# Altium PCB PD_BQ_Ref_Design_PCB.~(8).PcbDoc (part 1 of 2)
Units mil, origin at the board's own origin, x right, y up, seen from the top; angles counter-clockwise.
Board outline 2000 x 3000 mil, 4 copper layers (Top Layer, Signal Layer 1, Signal Layer 2, Bottom Layer), stack 61.2 mil thick; 108 components, 54 nets, 333 pads, 494 vias.
Unrouted connection lines stored in the file: 227.
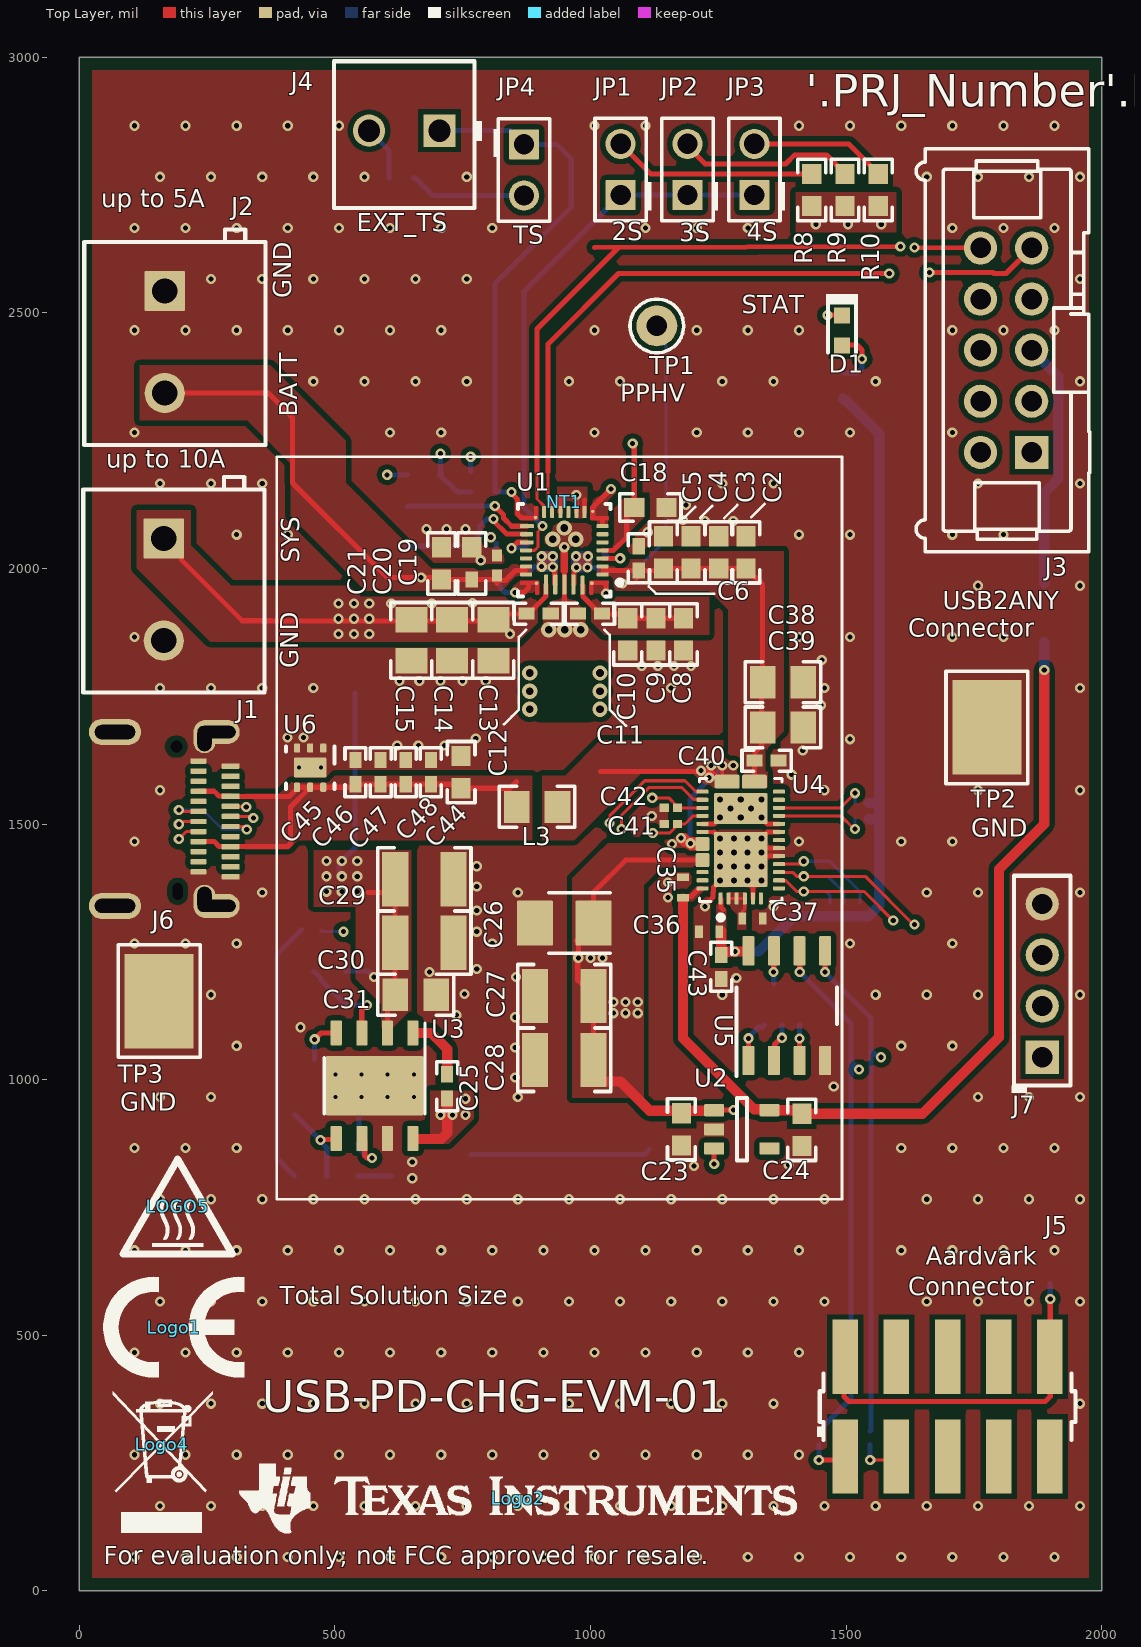
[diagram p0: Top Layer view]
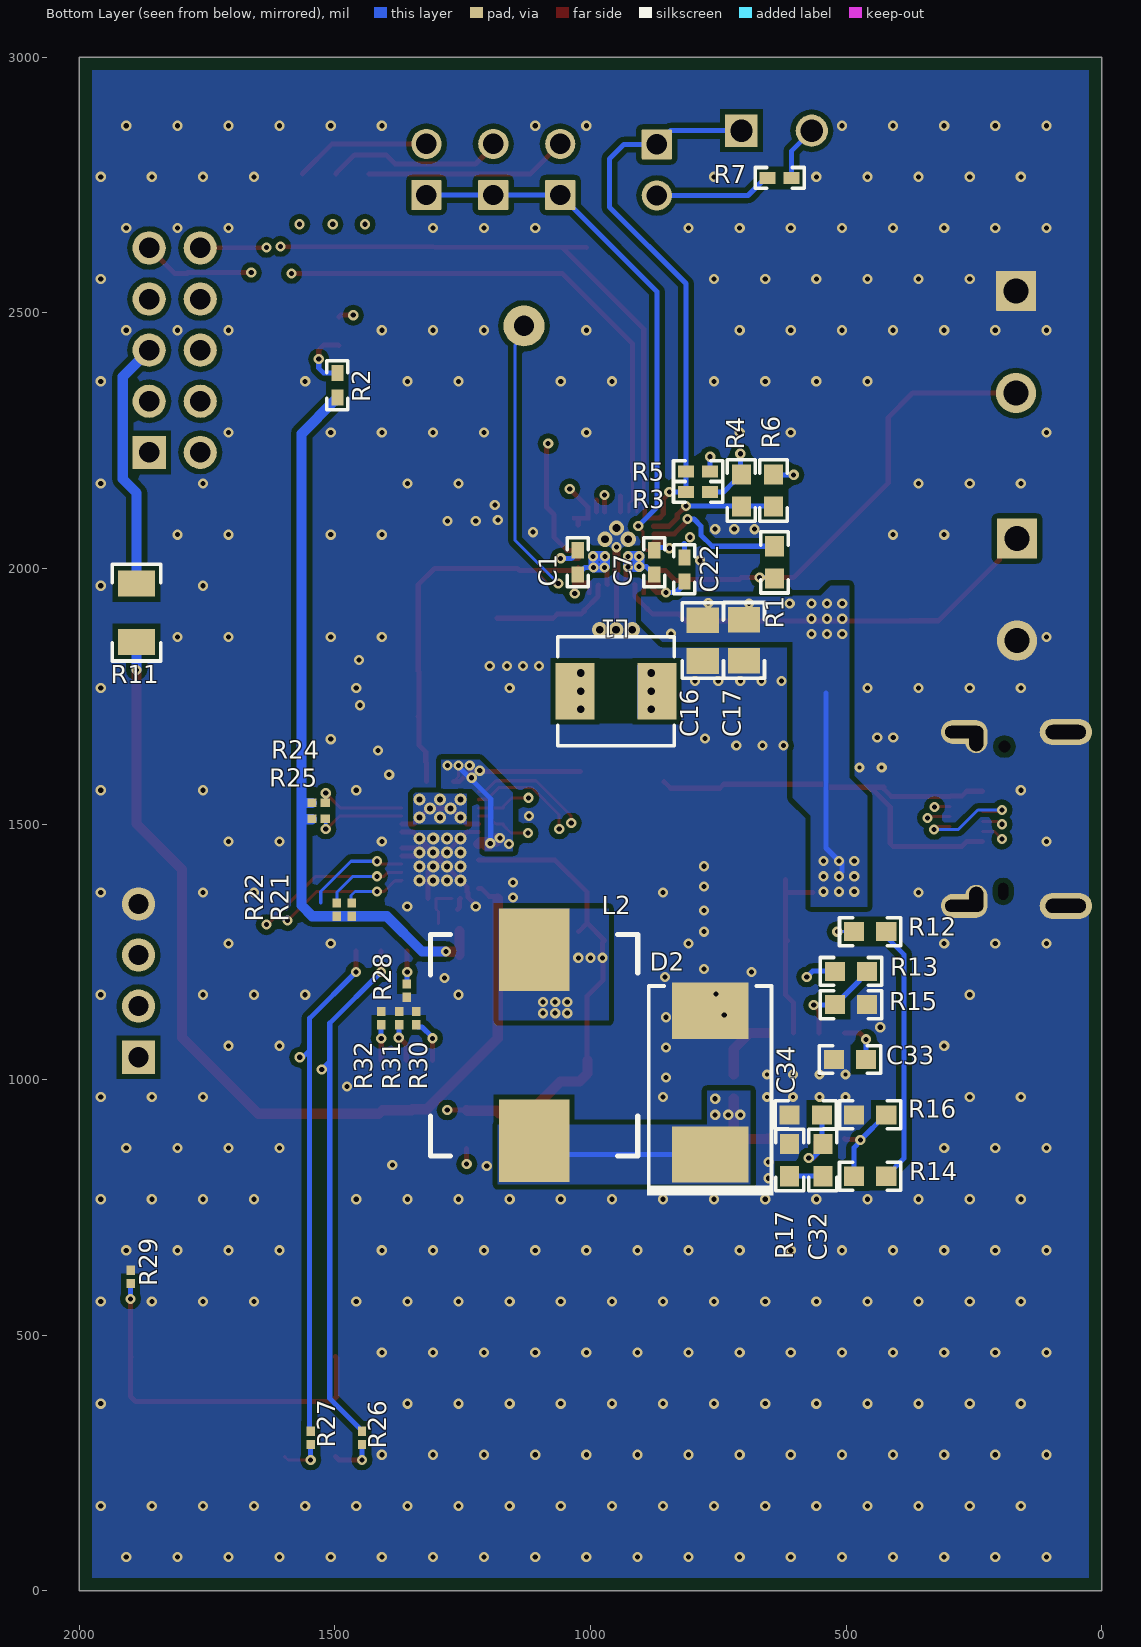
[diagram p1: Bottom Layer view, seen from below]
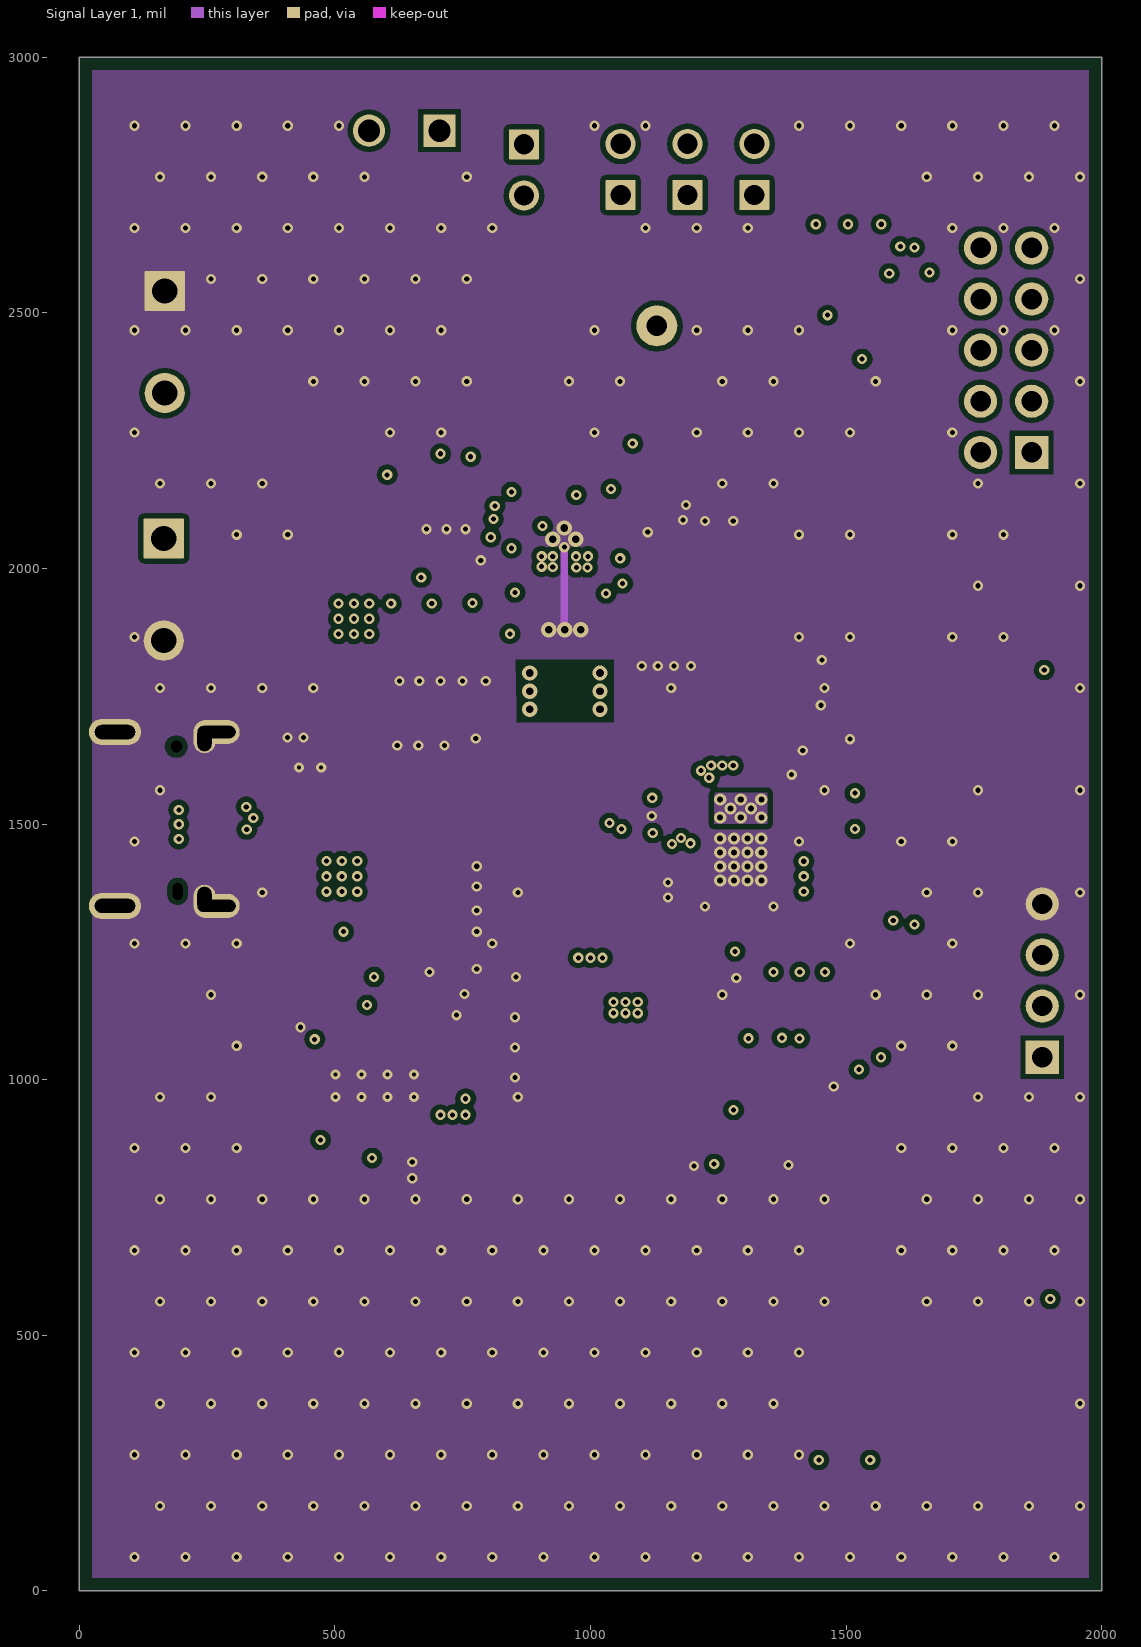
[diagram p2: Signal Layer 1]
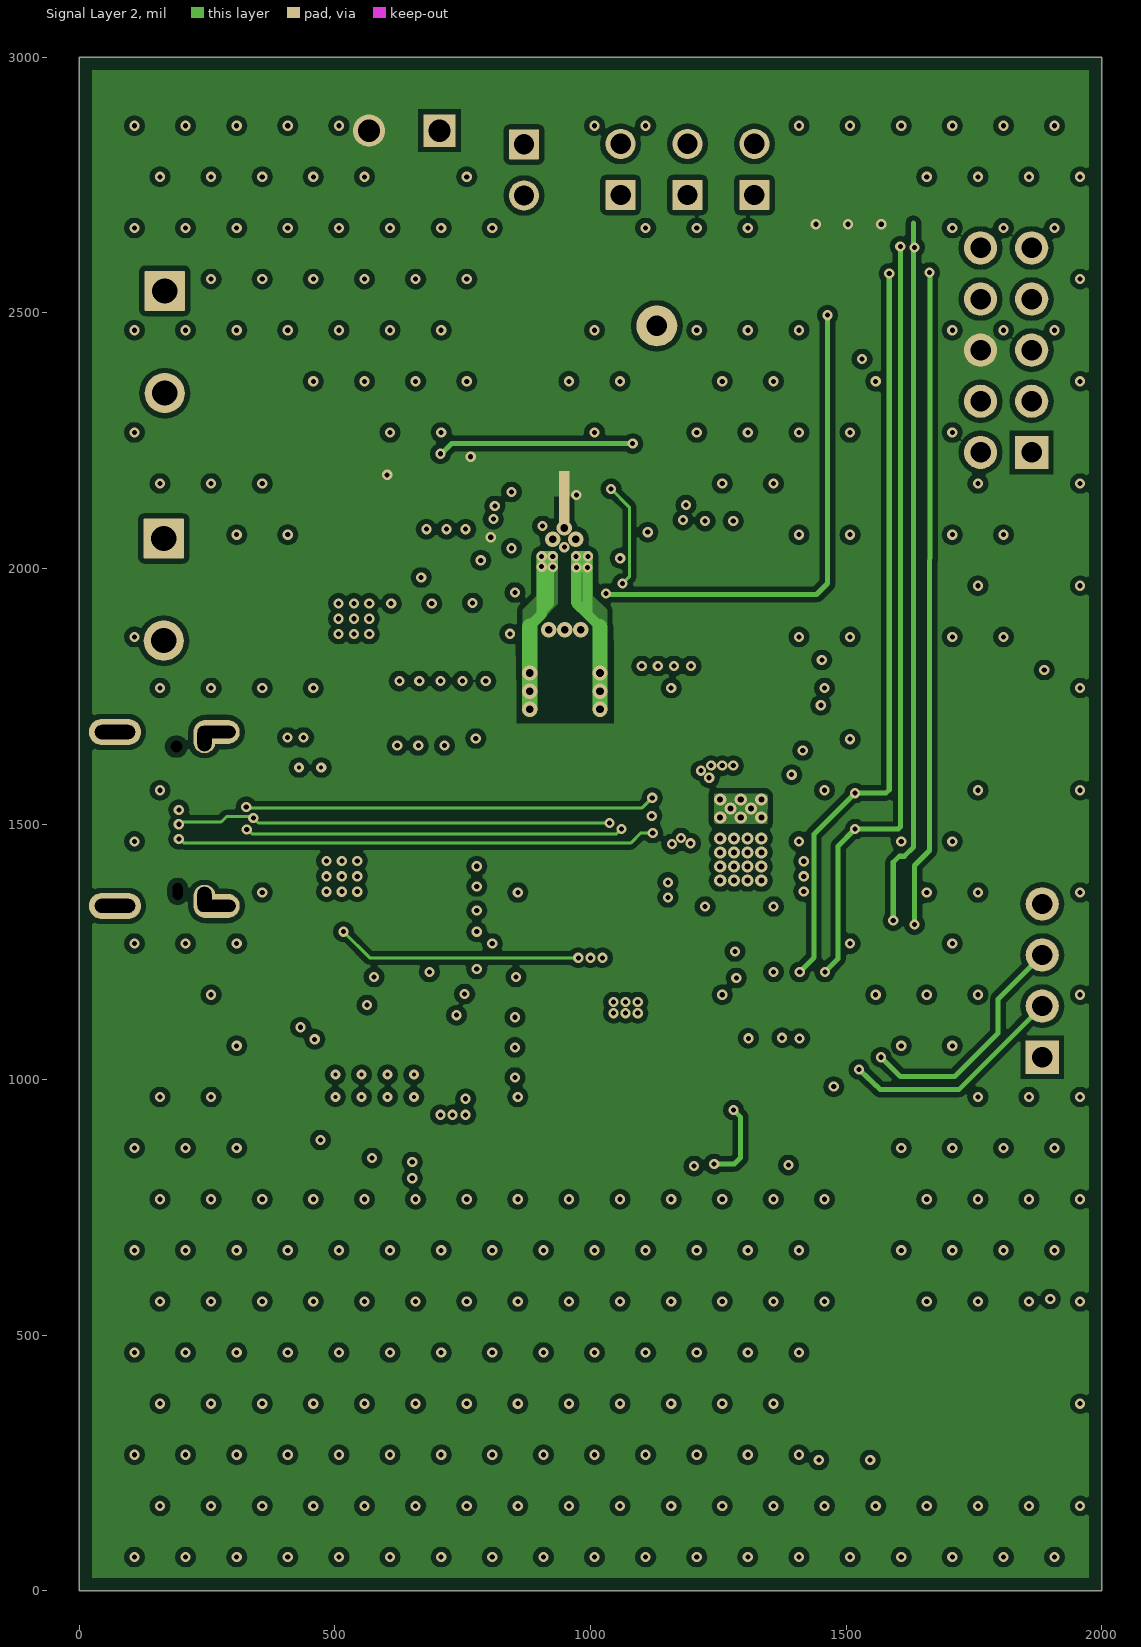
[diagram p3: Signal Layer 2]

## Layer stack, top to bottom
Top Solder: solder mask 0.4, Solder Resist, Dk 3.5
Top Layer: signal copper 2.8
Dielectric 1: prepreg 12, FR-4 High TG, Dk 4.2
Signal Layer 1: signal copper 2.8
Dielectric2: core 26, FR-4 High TG, Dk 4.2
Signal Layer 2: signal copper 2.8
Dielectric3: prepreg 12, FR-4 High TG, Dk 4.2
Bottom Layer: signal copper 2.8
Bottom Solder: solder mask 0.4, Solder Resist, Dk 3.5

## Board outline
0,0 2000,0 2000,3000 0,3000

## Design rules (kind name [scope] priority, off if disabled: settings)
AcuteAngle [All] p1: minimum=4.50000000000000E+0001 checktracksonly=FALSE
AssemblyTestPointUsage [All] p1: valid=2
BoardOutlineClearance BoardOutlineClearance_MountingHoles [OnCopper and InComponentClass('Mounting Holes')] p1: gap=39.37 ignorepadtopadclearanceinfootprint=FALSE
BoardOutlineClearance BoardOutlineClearance_Poly [OnCopper and IsPoly] p2: gap=25 ignorepadtopadclearanceinfootprint=FALSE
BoardOutlineClearance [OnCopper and Not InComponentClass('Logo') and not InComponentClass('FiducialMark') and not InRegion(1000,500,4000,800) and not InPoly] p3: gap=15 ignorepadtopadclearanceinfootprint=FALSE
Clearance Clearance_Keepouts [((IsTrack Or IsArc) And Not InPoly) And IsFree and IsKeepOut vs ((IsTrack Or IsArc) And Not InPoly) And IsFree and IsKeepOut] p1: gap=0 ignorepadtopadclearanceinfootprint=FALSE
Clearance Clearance_Poly [InPolygon] p2: gap=10 ignorepadtopadclearanceinfootprint=TRUE
Clearance Clearance_FiducialMark [IsKeepOut and InComponentClass('FiducialMark') vs IsPad and InComponentClass('FiducialMark')] p3: gap=0 ignorepadtopadclearanceinfootprint=FALSE
Clearance [All] p4: gap=5 ignorepadtopadclearanceinfootprint=TRUE
ComponentClearance ComponentClearance_MountingHoles_FiducialMarks [InComponentClass('Mounting Holes') vs InComponentClass('FiducialMark')] p1: gap=50 collisioncheckmode=3 verticalgap=10 showdistances=FALSE
ComponentClearance ComponentClearance_Shunt [InComponentClass('Header') vs InComponentClass('Shunt')] p2: gap=0 collisioncheckmode=3 verticalgap=0 showdistances=FALSE
ComponentClearance ComponentClearance_Logo [InComponentClass('Logo')] p3: gap=50 collisioncheckmode=3 verticalgap=10 showdistances=FALSE
ComponentClearance ComponentClearance_ScrewToNut [(HasFootprint('NY PMS 440 0025 PH')) vs (HasFootprint('Keystone_1902C'))] p4: gap=5 collisioncheckmode=3 verticalgap=10 showdistances=FALSE
ComponentClearance ComponentClearance_MountingHoles [InComponentClass('Mounting Holes')] p5: gap=250 collisioncheckmode=3 verticalgap=100000 showdistances=FALSE
ComponentClearance ComponentClearance_SmallPassives [HasFootprint('0201*') or HasFootprint('0402*') or HasFootprint('0508') or HasFootprint('0603*') or HasFootprint('0612') or HasFootprint('0805*') or HasFootprint('0815*') or HasFootprint('0830*') or HasFootprint('1206*') or HasFootprint('1210*') or HasFootprint('1808*') or HasFootprint('1812*') or HasFootprint('1825*') or HasFootprint('2010*') or HasFootprint('2220*') or HasFootprint('2225*') or HasFootprint('2512*') or HasFootprint('2728*') or HasFootprint('3518*') vs HasFootprint('0201*') or HasFootprint('0402*') or HasFootprint('0508') or HasFootprint('0603*') or HasFootprint('0612') or HasFootprint('0805*') or HasFootprint('0815*') or HasFootprint('0830*') or HasFootprint('1206*') or HasFootprint('1210*') or HasFootprint('1808*') or HasFootprint('1812*') or HasFootprint('1825*') or HasFootprint('2010*') or HasFootprint('2220*') or HasFootprint('2225*') or HasFootprint('2512*') or HasFootprint('2728*') or HasFootprint('3518*')] p6: gap=14.96 collisioncheckmode=3 verticalgap=10 showdistances=FALSE
ComponentClearance ComponentClearance_THtoSMT [IsThruComponent vs IsSMTComponent] p7: gap=40 collisioncheckmode=3 verticalgap=30 showdistances=FALSE
ComponentClearance ComponentClearance_THtoTH [IsThruComponent vs IsThruComponent] p8: gap=30 collisioncheckmode=3 verticalgap=30 showdistances=FALSE
ComponentClearance [All] p9: gap=20 collisioncheckmode=3 verticalgap=10 showdistances=FALSE
DiffPairsRouting [All] p1: maxlimit=100 minlimit=10 mostfreqgap=10 toplayer_minwidth=15 toplayer_maxwidth=15 toplayer_prefwidth=15 midlayer1_minwidth=15 midlayer1_maxwidth=15 midlayer1_prefwidth=15 midlayer2_minwidth=15 midlayer2_maxwidth=15 midlayer2_prefwidth=15 bottomlayer_minwidth=15 bottomlayer_maxwidth=15 bottomlayer_prefwidth=15 maxuncoupledlength=1000
FabricationTestPointUsage TestPointUsage [All] p1: valid=2 allowmultiple=FALSE
FabricationTestpoint Testpoint [All] p1: side=3 testpointundercomponent=TRUE minsize=40 maxsize=100 preferedsize=60 minholesize=0 maxholesize=40 preferedholesize=32 testpointgrid=1 allowsidetop=TRUE allowsidebottom=TRUE usegrid=TRUE gridtolerance=0.01
FanoutControl Fanout_LCC [IsLCC] p1: bgadir=Out bgaviamode=Centered fanoutstyle=Auto fanoutdirection=Alternating viagrid=1 // Fanout_LCC (Default Rule)
FanoutControl Fanout_BGA [IsBGA] p2: bgadir=Out bgaviamode=Centered fanoutstyle=Auto fanoutdirection=Alternating viagrid=1 // Fanout_BGA (Default Rule)
FanoutControl Fanout_Default [All] p4: bgadir=Out bgaviamode=Centered fanoutstyle=Auto fanoutdirection=Alternating viagrid=1 // Fanout_Default (Default Rule)
FanoutControl Fanout_Small [(CompPinCount < 5)] p5: bgadir=Out bgaviamode=Centered fanoutstyle=Auto fanoutdirection=OutThenIn viagrid=1 // Fanout_Small (Default Rule)
HoleSize [All] p1: absolutevalues=TRUE maxlimit=251 minlimit=7.87 maxpercent=80.000 minpercent=20.000
MinimumAnnularRing MinimumAnnularRing_ThermalPadVias [IsVia and InAnyComponent] p1: minimumring=5.91
MinimumAnnularRing [All] p2: minimumring=5
MinimumSolderMaskSliver MinimumSolderMaskSliver_Logo [InComponentClass('Logo') vs InComponentClass('Logo')] p1: minsoldermaskwidth=0.7
MinimumSolderMaskSliver [All] p2: minsoldermaskwidth=3
PlaneConnect [All] p1: planeconnectstyle=Relief reliefexpansion=10 reliefentries=4 reliefconductorwidth=10 reliefairgap=10
PolygonConnect [All] p1: connectstyle=Direct reliefconductorwidth=10 reliefentries=4 polygonreliefangle="90 Angle" airgapwidth=10
RoutingVias ThermalPadVias [IsVia and InAnyComponent] p1: holewidth=7.87 width=19.68 viastyle="Through Hole" minholewidth=7.87 minwidth=19.68 maxholewidth=12.99 maxwidth=23.62
RoutingVias [All] p2: holewidth=10 width=20 viastyle="Through Hole" minholewidth=5 minwidth=10 maxholewidth=40 maxwidth=65
SilkToBoardRegionClearance [Not ((IsComment or IsDesignator) And (Hide <> 'False')) and not InRegion(1000,500,4000,800)] p1:
SilkToSilkClearance SilkToSilkClearance_Pb-FreeLogo [(HasFootprint('Pb-Free_Overlay_Medium') OR HasFootprint('Pb-Free_Overlay_Small')) vs (HasFootprint('Pb-Free_Overlay_Medium') OR HasFootprint('Pb-Free_Overlay_Small'))] p1: silktosilkclearance=0
SilkToSilkClearance [All] p2: silktosilkclearance=1
SilkToSolderMaskClearance SilkToComponentPadClearance [(IsPad or IsFill or IsRegion) and InAnycomponent] p1: minsilkscreentomaskgap=3 clearancetoexposedcopper=TRUE
SilkToSolderMaskClearance "Silk to Solder Mask Opening" [All] p2: minsilkscreentomaskgap=3.94 clearancetoexposedcopper=FALSE
SolderMaskExpansion [All] p1: expansion=1.97
UnRoutedNet [All] p1: checkbadconnections=TRUE
Width [All] p1: maxlimit=100 minlimit=6 preferedwidth=10 checkconnectedcopper=TRUE
14 further rules are at their usual default settings.

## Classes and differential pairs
component class Logo: Logo2
component class Type_C_Port: C44 C45 C46 C47 C48 J6 L3 U6
component class TPS25750D: C35 C36 C37 C38 C39 C40 C41 C42 C43 J5 J7 R21 R22 R24 R25 R26 R27 R28 R29 R30 R31 R32 U4 U5
component class Power_5V_3.3V: C23 C24 C25 C26 C27 C28 C29 C30 C31 C32 C33 C34 D2 L2 R12 R13 R14 R15 R16 R17 U2 U3
component class Header: J5 J7 JP1 JP2 JP3 JP4
component class BQ25792: C1 C2 C3 C4 C5 C6 C7 C8 C9 C10 C11 C12 C13 C14 C15 C16 C17 C18 C19 C20 C21 C22 D1 J1 J2 J3 J4 JP1 JP2 JP3 JP4 L1 NT1 R1 R2 R3 R4 R5 R6 R7 R8 R9 R10 R11 TP1 TP2 TP3 U1
component class PD_BQ_Ref_Design_Hardware: Logo1 Logo2 Logo3 Logo4 LOGO5 ZZ1
component class AssemblyNote: ZZ1

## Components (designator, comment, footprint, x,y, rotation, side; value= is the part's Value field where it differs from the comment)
C1 "GRM155R71E473KA88D" 0402 1024.72,2011.81 r270 bottom value=0.047uF
C2 "GRT188R61E106ME13D" 0603#1 1304.25,2031.5 r270 top value=10uF
C3 "GRT188R61E106ME13D" 0603#1 1251.1,2031.5 r270 top value=10uF
C4 "GRT188R61E106ME13D" 0603#1 1196.97,2031.5 r270 top value=10uF
C5 "GRT188R61E106ME13D" 0603#1 1142.83,2031.5 r270 top value=10uF
C6 "C1005X7R1H104K050BE" 0402 1094.61,2019.69 r90 top value=0.1uF
C7 "GRM155R71E473KA88D" 0402 875.12,2011.81 r270 bottom value=0.047uF
C8 "GRT188R61E106ME13D" 0603#1 1182.2,1871.06 r90 top value=10uF
C9 "GRT188R61E106ME13D" 0603#1 1128.07,1871.06 r90 top value=10uF
C10 "GRT188R61E106ME13D" 0603#1 1072.95,1871.06 r90 top value=10uF
C11 "C1005X7R1H104K050BE" 0402 999.13,1911.42 r180 top value=0.1uF
C12 "C1005X7R1H104K050BE" 0402 898.74,1911.42 r0 top value=0.1uF
C13 "C2012X5R1E106K125AB" 0805_HV 810.16,1859.25 r270 top value=10uF
C14 "C2012X5R1E106K125AB" 0805_HV 729.45,1859.25 r270 top value=10uF
C15 "C2012X5R1E106K125AB" 0805_HV 649.72,1859.25 r270 top value=10uF
C16 "C2012X5R1E106K125AB" 0805_HV 780.16,1858.9 r270 bottom value=10uF
C17 "C2012X5R1E106K125AB" 0805_HV 699.45,1859.25 r270 bottom value=10uF
C18 "GRM188R61C475KAAJ" 0603#1 1117.24,2119.09 r0 top value=4.7uF
C19 "C1005X7R1H104K050BE" 0402L 816.93,2005.91 r90 top value=0.1uF
C20 "GRT188R61E106ME13D" 0603#2 767.83,2009.84 r90 top value=10uF
C21 "GRT188R61E106ME13D" 0603#1 708.78,2009.84 r90 top value=10uF
C22 "C0402C102K5RACTU" 0402 816.06,1998.03 r90 bottom value=1000pF
C23 "GRT188R61E106ME13D" 0603#1 1178.15,902.65 r90 top value=10uF
C24 "GRT188R61E106ME13D" 0603#1 1413.55,901.67 r90 top value=10uF
C25 "C1005X7R1H104K050BE" 0402 719.74,986.76 r270 top value=0.1uF
C26 "T520B107M006ATE015" 3528-21 948.82,1306.1 r180 top value=100uF
C27 "GRM32ER61A476KE20L" 1210_270 948.82,1163.39 r180 top value=47uF
C28 "GRM32ER61A476KE20L" 1210_270 948.82,1038.39 r180 top value=47uF
C29 "GRM32ER71H475KA88L" 1210_270 675.2,1391.73 r0 top value=4.7uF
C30 "GRM32ER71H475KA88L" 1210_270 675.2,1267.72 r0 top value=4.7uF
C31 "GRM216R71H103KA01D" 0805_HV 658.28,1166.04 r0 top value=0.01uF
C32 "GRM188R71H222KA01D" 0603#1 545.28,842.52 r270 bottom value=2200pF
C33 "06031C103KAT2A" 0603#1 492.13,1039.37 r0 bottom value=0.01uF
C34 "GRM1885C1H220JA01D" 0603#1 578.74,931.1 r0 bottom value=22pF
C35 "CL05A106MP5NUNC" 0402_070 1181.1,1375.98 r90 top value=10uF
C36 "CL05A106MP5NUNC" 0402_070 1232.28,1289.37 r180 top value=10uF
C37 "CL05A106MP5NUNC" 0402_070 1316.93,1314.96 r0 top value=10uF
C38 "C2012X5R1V226M125AC" 0805_HV 1376.78,1777.48 r0 top value=22uF
C39 "C2012X5R1V226M125AC" 0805_HV 1376.78,1688.9 r0 top value=22uF
C40 "GMK105BJ104KV-F" 0402 1344.49,1624.02 r0 top value=0.1uF
C41 "GRM033R71H331KA12D" 0201_033 1157.48,1500 r180 top value=330pF
C42 "GRM033R71H331KA12D" 0201_033 1157.48,1531.5 r180 top value=330pF
C43 "GMK105BJ104KV-F" 0402 1255.91,1220.47 r270 top value=0.1uF
C44 "GRM188R6YA475KE15D" 0603#1 747.05,1601.38 r90 top value=4.7uF
C45 "C0402C103J5RACTU" 0402 540.35,1601.38 r270 top value=0.01uF
C46 "C0402C103J5RACTU" 0402 589.57,1601.38 r270 top value=0.01uF
C47 "C0402C103J5RACTU" 0402 638.78,1601.38 r270 top value=0.01uF
C48 "C0402C103J5RACTU" 0402 687.99,1601.38 r270 top value=0.01uF
D1 "LTST-C190GKT" LED_LTST-C190 1492.13,2465.55 r90 top value=Green
D2 "CDBC540-G" SMC 765.75,994.09 r90 bottom value=40V
J1 "ED120/2DS" On-Shore_ED120_2DS 165.35,1958.66 r270 top
J2 "ED120/2DS" On-Shore_ED120_2DS 167.32,2442.91 r270 top
J3 "N2510-6002-RB" CONN_2510-6002 1813.19,2426.97 r90 top
J4 "0393570002" MOLEX_39357-0002 635.83,2856.3 r180 top
J5 "TSM-105-01-L-DV-P" Samtec_TSM-105-01-x-DV 1698.64,360.31 r90 top
J6 "DX07S024JJ2R1300" JAE_DX07S024JJ2R1300 -0.98,1509.84 r270 top
J7 "PEC04SAAN" SULLINS_PEC04SAAN 1883.86,1193.7 r90 top
JP1 "Header_2x1" CONN_PEC02SAAN 1059.06,2780.51 r90 top
JP2 "Header_2x1" CONN_PEC02SAAN 1189.96,2780.51 r90 top
JP3 "Header_2x1" CONN_PEC02SAAN 1320.87,2780.51 r90 top
JP4 "Header_2x1" CONN_PEC02SAAN 870.08,2779.53 r270 top
L1 "IHLP2020BZER1R0M11" IHLP-2020BZ 949.92,1759.72 r180 bottom value=1uH
L2 "74437368047" WE-LHMI_1040 1110.24,1066.93 r90 bottom value=4.7uH
L3 "FBMJ2125HM210NT" 0805_HV 895.67,1533.46 r0 top value="21 ohm"
Logo1 "CE Mark" CE_Mark_5mm 185.04,515.75 r0 top
Logo2 "Texas Instruments" TI_Horizontal_Overlay_Small 858,181.1 r0 top
Logo3 "FCC disclaimer" FCC_disclaimer 3983.27,519.68 r0 top
Logo4 "WEEE logo" WEEE_Minimum 161.42,286.22 r0 top
LOGO5 "CAUTION HOT SURFACE" IEC_HotSurface_Small 192.52,751.97 r0 top
NT1 "Net-Tie" Net-Tie_20milWide_60milLong 948.82,2130.39 r90 top net-tie
R1 "RC0603FR-07100RL" 0603#1 639.76,2011.81 r90 bottom value=100
R2 "CRCW04022K21FKED" 0402 1495.08,2358.27 r270 bottom value=2.21k
R3 "Resistor" 0402 789.49,2149.61 r180 bottom value=5.23k
R4 "RC0603FR-07137KL" 0603#1 704.78,2152.56 r90 bottom value=137k
R5 "Resistor" 0402 789.49,2189.96 r0 bottom value=30.1k
R6 "RC0603FR-07100KL" 0603#1 641.92,2152.56 r270 bottom value=100k
R7 "Resistor" 0402 629.92,2763.78 r0 bottom value=10.0k
R8 "RC0603FR-076K04L" 0603#1 1433.07,2740.16 r90 top value=6.04k
R9 "CRCW060310K5FKEA" 0603#1 1498.03,2740.16 r90 top value=10.5k
R10 "CRCW060317K4FKEA" 0603#1 1562.99,2740.16 r90 top value=17.4k
R11 "ERJ-8ENF10R0V" 1206 1887.8,1913.39 r270 bottom value=10.0
R12 "CRCW060351R1FKEA" 0603#1 452.76,1289.37 r0 bottom value=51.1
R13 "CRCW0603665KFKEA" 0603#1 490.16,1211.61 r0 bottom value=665k
R14 "CRCW060310K2FKEA" 0603#1 452.76,811.02 r180 bottom value=10.2k
R15 "CRCW0603130KFKEA" 0603#1 490.16,1146.65 r0 bottom value=130k
R16 "CRCW06031K96FKEA" 0603#1 452.76,931.1 r180 bottom value=1.96k
R17 "CRCW060337K4FKEA" 0603#1 610.24,842.52 r270 bottom value=37.4k
R21 "CRCW02012K20FKED" 0201 1466.54,1332.68 r270 bottom value=2.20k
R22 "CRCW02012K20FKED" 0201 1496.06,1332.68 r270 bottom value=2.20k
R24 "CRCW02012K20FKED" 0201 1531.5,1541.34 r180 bottom value=2.20k
R25 "CRCW02012K20FKED" 0201 1531.5,1509.84 r180 bottom value=2.20k
R26 "CRCW02010000Z0ED" 0201 1446.85,299.21 r270 bottom value=0
R27 "CRCW02010000Z0ED" 0201 1547.24,299.21 r270 bottom value=0
R28 "CRCW020110K0FKED" 0201 1359.25,1174.21 r90 bottom value=10.0k
R29 "CRCW02010000Z0ED" 0201 1899.61,614.17 r270 bottom value=0
R30 "CRCW020110K0FKED" 0201 1340.55,1120.08 r270 bottom value=10.0k
R31 "CRCW020110K0FKED" 0201 1374.02,1120.08 r270 bottom value=10.0k
R32 "CRCW020110K0FKED" 0201 1409.45,1120.08 r270 bottom value=10.0k
TP1 "5000" Keystone5000 1129.92,2474.41 r90 top
TP2 "5016" Testpoint_Keystone_Compact 1775.59,1688.98 r90 top
TP3 "5016" Testpoint_Keystone_Compact 156.5,1153.54 r270 top
U1 "BQ25792RQM" RQM0029A-MFG 948.94,2035.33 r180 top
U2 "TLV75533PDBVR" DBV0005A_N 1296.26,902.65 r0 top
U3 "TPS54531DDAR" DDA0008E_L 577.76,987.91 r270 top
U4 "TPS25750DRJK" RJK0038B-C01-MFG 1294.1,1468.68 r90 top
U5 "CAT24C256WI-G" SOIC-8 1384.05,1144.61 r90 top
U6 "TVS2200DRVR" DRV0006A 451.77,1610.24 r270 top
ZZ1 "This Assembly Note is for PCB labels only" AssemblyNoteLabel 185,3938 r0 top

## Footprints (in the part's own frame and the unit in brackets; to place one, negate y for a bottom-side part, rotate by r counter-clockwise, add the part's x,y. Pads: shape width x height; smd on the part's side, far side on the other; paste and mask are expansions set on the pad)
0201 [mm] "Data from Kemet datasheet CC101_COM dated 7/28/11"
  rect 0.46x0.42 smd: 1(-0.33,0) 2(0.33,0)
  body extent -0.31,-0.16 0.31,0.16, height 0.26
0201_033 [mm] "SMD, 2-Leads, Height 0.33mm"
  rect 0.46x0.42 smd: 1(-0.33,0) 2(0.33,0)
  body extent -0.31,-0.16 0.31,0.16, height 0.33
0402 [mm] "0402 from SM-752 data"
  rect 0.8x0.6 smd: 1(-0.6,0) 2(0.6,0)
  silkscreen extent -1.22,-0.52 1.22,0.52, body extent -0.55,-0.3 0.55,0.3, height 0.6
0402_070 [mil] "SMD, 2-Leads, Body 1.2x0.7mm, Height 0.7mm"
  rect 15x24 smd: 1(-20,0) 2(20,0)
  body extent -24,-14 24,14, height 28
0402L [mm] "0402 from SM-752 data"
  rect 0.6x0.5 smd: 1(-0.5,0) 2(0.5,0)
  body extent -0.55,-0.3 0.55,0.3, height 0.6
0603#1 [mm] "0603 from SM-752 data"
  rect 1x0.95 smd: 1(-0.8,0) 2(0.8,0)
  silkscreen extent -1.52,-0.69 1.52,0.69, body extent -0.87,-0.47 0.87,0.47, height 1
0603#2 [mm] "0603 from SM-752 data"
  rect 0.8x0.6 smd: 1(-0.8,0)
  rect 1x0.95 smd: 2(0.8,0)
  silkscreen extent -1.52,-0.69 1.52,0.69, body extent -0.87,-0.47 0.87,0.47, height 1
0805_HV [mil] "0805 with 30mil clearance between pads"
  rect 50x63 smd: 1(-40,0) 2(40,0)
  silkscreen extent -74,-40 74,40, body extent -43,-29 43,29, height 57
1206 [mm] "1206 from SM-752 data"
  rect 1.3x1.85 smd: 1(-1.45,0) 2(1.45,0)
  silkscreen extent -2.4,-1.21 2.4,1.21, body extent -1.7,-0.9 1.7,0.9, height 1.35
1210_270 [mm] "1210"
  rect 1.3x2.7 smd: 1(-1.45,0) 2(1.45,0)
  silkscreen extent -2.32,-1.57 2.32,1.57, body extent -1.7,-1.35 1.7,1.35, height 2.7
3528-21 [mm] "Medium Density IPC, based on Kemet datasheet 2016-10-20"
  rrect6% 1.8x2.23 smd: 1(-1.46,0) 2(1.46,0)
  silkscreen extent -2.29,-1.5 0.76,1.5, body extent -1.85,-1.5 1.85,1.5, height 2.12
AssemblyNoteLabel [mil] "Assembly Note for PCB Labels"
CE_Mark_5mm [mil] "Minimum text height for CE Mark"
  silkscreen extent -138,-98 138,98
CONN_2510-6002 [mm] "3M 2500 series TS-0770-L December 15, 2011"
  rect 1.65x1.65 hole 1.016: 1(-5.08,-1.27)
  round 1.65 hole 1.016: 2(-5.08,1.27) 3(-2.54,-1.27) 4(-2.54,1.27) 5(0,-1.27) 6(0,1.27) 7(2.54,-1.27) 8(2.54,1.27) 9(5.08,-1.27) 10(5.08,1.27)
  silkscreen extent -10.01,-4.17 10.01,4.47, body extent -10.01,-4.11 10.01,4.52, height 9.92
CONN_PEC02SAAN [mm] "SULLINS"
  rrect7% 1.5x1.5 hole 1.016: 1(-1.27,0)
  round 1.5 hole 1.016: 2(1.27,0)
  silkscreen extent -2.54,-1.52 2.54,1.27, body extent -2.54,-1.27 2.54,1.27, height 8.38
DBV0005A_N [mm] "SOT23, 5-Leads, Body 2.9x1.6mm, Pitch 0.95mm, Lead Span 2.8mm, IPC Medium Density"
  rrect17% 1x0.6 smd: 1(-1.375,0.95) 2(-1.375,0) 3(-1.375,-0.95) 4(1.375,-0.95) 5(1.375,0.95)
  silkscreen extent -0.25,-1.55 0.25,1.55, body extent -1.42,-1.46 1.42,1.46, height 1.09
DDA0008E_L [mm]
  rrect18% 1.25x0.55 smd: 1(-2.625,1.905) 2(-2.625,0.635) 3(-2.625,-0.635) 4(-2.625,-1.905) 5(2.625,-1.905) 6(2.625,-0.635) 7(2.625,0.635) 8(2.625,1.905)
  rrect7% 2.95x4.9 smd: 9(0,0)
  rrect4% 2.4x3.1 on Top Paste: 9(0,0)
  rrect4% 2.4x3.1 on Top Solder: 9(0,0)
  silkscreen extent -3.13,-2.5 1.4,2.5, body extent -3,-2.45 3,2.45, height 1.57
DRV0006A [mm] "SON, 6-Leads, Body 2x2mm, Pitch 0.65mm, Thermal Pad 1.6x1mm, TI Recommended"
  rrect33% 0.45x0.3 smd: 1(-0.975,0.65) 2(-0.975,0) 3(-0.975,-0.65) 4(0.975,-0.65) 5(0.975,0) 6(0.975,0.65)
  rrect14% 1x0.7 on Top Paste: 7(0,0.45) 7(0,-0.45)
  rrect10% 1x1.6 smd paste-0.5: 7(0,0)
  silkscreen extent -1.05,-1.2 1.05,1.2, body extent -1.05,-1.05 1.05,1.05, height 0.81
FCC_disclaimer [mil]
IEC_HotSurface_Small [mil]
  silkscreen extent -107,-93 107,92
IHLP-2020BZ [mm] "Vishay Dale recommended land pattern.  Document 34261 rev 12-Sept-13"
  rect 1.915x2.79 smd: 1(-2.037,0) 2(2.037,0)
  silkscreen extent -2.9,-2.7 2.9,2.7, body extent -2.87,-2.72 2.87,2.72, height 2
JAE_DX07S024JJ2R1300 [mm] "Receptacle, USB 3.1 Type C, R/A, SMT"
  rrect37% 0.27x0.9 smd: A1(-2.625,7.55) A2(-2.125,7.55) A3(-1.625,7.55) A4(-1.125,7.55) A5(-0.625,7.55) A6(-0.125,7.55) A7(0.375,7.55) A8(0.875,7.55) A9(1.375,7.55) A10(1.875,7.55) A11(2.375,7.55) A12(2.875,7.55)
  round 0.3 hole 0.6 unplated: ALIGN1(-3.6,4.85)
  rrect100% 0.55x0.3 hole 0.5 slot 0.85 at 0 deg unplated: ALIGN2(3.6,4.915)
  rrect37% 0.27x0.8 smd: B1(2.625,5.95) B2(2.125,5.95) B3(1.625,5.95) B4(1.125,5.95) B5(0.625,5.95) B6(0.125,5.95) B7(-0.375,5.95) B8(-0.875,5.95) B9(-1.375,5.95) B10(-1.875,5.95) B11(-2.375,5.95) B12(-2.875,5.95)
  rrect100% 1.2x2.3 hole 0.6 slot 1.9 at 90 deg: S1(-4.32,6.85) S2(4.32,6.85)
  rrect100% 1.45x1.1 hole 0.7 slot 1.25 at 0 deg: S1(-3.995,6.25) S2(3.995,6.25)
  rrect100% 1.3x2.6 hole 0.7 slot 2 at 90 deg: S3(-4.32,1.8) S4(4.32,1.8)
  body extent -4.47,-0.5 4.47,7.67, height 3.14
Keystone5000 [mil] "For Keystone 500x miniature loop terminals"
  round 80 hole 40: 1(0,0)
  silkscreen extent -52,-52 52,52, body extent -49,-49 49,49, height 182
LED_LTST-C190 [mm] "Lite-On"
  rect 0.8x0.8 smd: 1(-0.75,0) 2(0.75,0)
  silkscreen extent -1.1,-0.8 1.8,0.8, body extent -0.85,-0.45 0.85,0.45, height 0.9
MOLEX_39357-0002 [mm] "Terminal Block, 3.5 mm, 2x1, TH"
  rect 1.6x1.6 hole 1.1: 1(-1.75,0)
  round 1.6 hole 1.1: 2(1.75,0)
  silkscreen extent -3.86,-3.45 3.5,3.84, body extent -3.55,-3.45 3.56,3.84, height 8.51
Net-Tie_20milWide_60milLong [mil] "20mil net tie, no solder mask opening, no solder paste"
  rect 60x20 on Mid2: 1(-30,0) 2(30,0)
On-Shore_ED120_2DS [mm] "ONSHORE"
  rrect5% 2x2 hole 1.25: 1(-2.54,0)
  round 2 hole 1.25: 2(2.54,0)
  silkscreen extent -5.6,-4 5.12,5, body extent -5.78,-4 5.08,5, height 13
RJK0038B-C01-MFG [mm]
  rrect50% 0.6x0.2 smd: 1(-2.9,1) 2(-2.9,0.6) 3(-2.9,0.2) 4(-2.9,-0.2) 5(-2.9,-0.6) 6(-2.9,-1)
  rrect50% 0.2x0.6 smd: 7(-2.4,-1.9) 8(-2,-1.9) 9(-1.6,-1.9) 10(-1.2,-1.9) 11(-0.8,-1.9) 12(-0.4,-1.9) 13(0,-1.9) 14(0.4,-1.9) 15(0.8,-1.9) 16(1.2,-1.9) 17(1.6,-1.9) 18(2,-1.9) 19(2.4,-1.9) 26(2.4,1.9) 27(2,1.9) 28(1.6,1.9) 29(1.2,1.9) 30(0.8,1.9) 31(0.4,1.9) 36(-1.6,1.9) 37(-2,1.9) 38(-2.4,1.9)
  rrect29% 0.7x1.253 smd: 20-21-22(2.9,-0.677) 23-24-25(2.9,0.677)
  rrect29% 0.7x0.7 smd: 32-33(-0.2,1.9) 34-35(-1,1.9)
  rrect4% 2.72x2.65 smd: 39(-0.965,0)
  rrect7% 1.53x2.65 smd: 40(1.56,0)
  silkscreen extent -3.97,-2.05 3.05,2.05, body extent -3.3,-2.3 3.35,2.35, height 0.25
RQM0029A-MFG [mm]
  round 0.192 smd: 1(-1.369,1.631)
  rrect50% 0.6x0.2 smd: 2(-1.9,1.2) 3(-1.9,0.8) 4(-1.9,0.4) 5(-1.9,0) 6(-1.9,-0.4) 7(-1.9,-0.8) 8(-1.9,-1.2) 20(1.9,0) 21(1.9,0.4) 22(1.9,0.8) 23(1.9,1.2)
  round 0.158 smd: 9(-1.412,-1.937)
  rrect50% 0.2x0.6 smd: 10(-1,-1.9) 11(-0.6,-1.9) 12(-0.2,-1.9) 13(0.2,-1.9) 14(0.6,-1.9) 15(1,-1.9)
  round 0.175 smd: 16(1.431,-1.631) 24(1.381,1.631)
  rrect50% 0.7x0.2 smd: 17(1.85,-1.2)
  rrect50% 0.65x0.2 smd: 18(1.875,-0.8)
  rrect50% 0.68x0.2 smd: 19(1.86,-0.4)
  rrect50% 0.2x1 smd: 25(0.9,1.7) 26(0.45,1.7) 27(0,1.7) 28(-0.45,1.7)
  rrect50% 0.2x0.95 smd: 29(-0.9,1.725)
  Top Layer region: 2.2,1.65 2.196,1.669 2.185,1.685 2.169,1.696 2.15,1.7 2.15,1.7 1.45,1.7 1.45,2.15 1.446,2.169 1.435,2.185 1.419,2.196 1.4,2.2 1.4,2.2 1.3,2.2 1.275,2.193 1.257,2.175 1.25,2.15 1.25,2.15 1.25,1.55 1.254,1.531 1.265,1.515 1.281,1.504 1.3,1.5 1.3,1.5 2.15,1.5 2.169,1.504 2.185,1.515 2.196,1.531 2.2,1.55 2.2,1.55
  Top Layer region: 2.2,-1.65 2.193,-1.675 2.175,-1.693 2.15,-1.7 2.15,-1.7 1.5,-1.7 1.5,-2.15 1.496,-2.169 1.485,-2.185 1.469,-2.196 1.45,-2.2 1.45,-2.2 1.35,-2.2 1.325,-2.193 1.307,-2.175 1.3,-2.15 1.3,-2.15 1.3,-1.55 1.304,-1.531 1.315,-1.515 1.331,-1.504 1.35,-1.5 1.35,-1.5 2.15,-1.5 2.169,-1.504 2.185,-1.515 2.196,-1.531 2.2,-1.55 2.2,-1.55
  Top Layer region: -2.2,-1.65 -2.193,-1.675 -2.175,-1.693 -2.15,-1.7 -2.15,-1.7 -1.5,-1.7 -1.5,-2.15 -1.496,-2.169 -1.485,-2.185 -1.469,-2.196 -1.45,-2.2 -1.45,-2.2 -1.35,-2.2 -1.331,-2.196 -1.315,-2.185 -1.304,-2.169 -1.3,-2.15 -1.3,-2.15 -1.3,-1.55 -1.304,-1.531 -1.315,-1.515 -1.331,-1.504 -1.35,-1.5 -1.35,-1.5 -2.15,-1.5 -2.169,-1.504 -2.185,-1.515 -2.196,-1.531 -2.2,-1.55 -2.2,-1.55
  Top Layer region: -2.2,1.65 -2.193,1.675 -2.175,1.693 -2.15,1.7 -2.15,1.7 -1.45,1.7 -1.45,2.15 -1.443,2.175 -1.425,2.193 -1.4,2.2 -1.4,2.2 -1.3,2.2 -1.275,2.193 -1.257,2.175 -1.25,2.15 -1.25,2.15 -1.25,1.55 -1.254,1.531 -1.265,1.515 -1.281,1.504 -1.3,1.5 -1.3,1.5 -2.15,1.5 -2.169,1.504 -2.185,1.515 -2.196,1.531 -2.2,1.55 -2.2,1.55
  silkscreen extent -2.88,-2.3 2.3,2.3, body extent -2.3,-2.3 2.3,2.3, height 0.25
Samtec_TSM-105-01-x-DV [mm] "Header, 2.54mm, 5x2, SMT"
  rect 3.68x1.27 smd: 1(-2.475,5.08) 2(2.475,5.08) 3(-2.475,2.54) 4(2.475,2.54) 5(-2.475,0) 6(2.475,0) 7(-2.475,-2.54) 8(2.475,-2.54) 9(-2.475,-5.08) 10(2.475,-5.08)
  silkscreen extent -1.65,-6.35 1.65,6.49, body extent -3.85,-6.35 3.85,6.35, height 9.65
SMC [mil] "Molded Diode, 2-Leads, Body 6.9x5.8mm, IPC Medium Density, based on OnSemi component dimensions and land patterns"
  rect 110x150 smd: 1(-140.49,0) 2(140.49,0)
  silkscreen extent -221,-123 189,124, body extent -156,-116 156,116, height 91
SOIC-8 [mm] "duplicate of SO-8.  SOIC, 8-Leads, Body 5.0x4.0mm (max), Pitch 1.27mm, IPC Medium Density"
  rrect17% 1.45x0.6 smd: 1(-2.725,1.905) 2(-2.725,0.635) 3(-2.725,-0.635) 4(-2.725,-1.905) 5(2.725,-1.905) 6(2.725,-0.635) 8(2.725,1.905) C(2.725,0.635)
  silkscreen extent -3.5,-2.5 0.9,2.5, body extent -3,-2.45 3,2.45, height 1.63
SULLINS_PEC04SAAN [mm] "SULLINS"
  rect 1.65x1.65 hole 1: 1(-3.81,0)
  round 1.65 hole 1: 2(-1.27,0) 3(1.27,0) 4(3.81,0)
  silkscreen extent -5.59,-1.4 5.21,1.52, body extent -5.21,-1.33 5.21,1.33, height 8.38
Testpoint_Keystone_Compact [mil] "Compact SMT test point"
  rect 185x135 smd: 1(0,0)
  silkscreen extent -110,-80 110,80, body extent -75,-56 75,56, height 91
TI_Horizontal_Overlay_Small [mil]
  silkscreen extent -545,-68 545,67
WE-LHMI_1040 [mm] "Wurth"
  rect 4.1x3.5 smd: 1(-4.75,0) 2(4.75,0)
  silkscreen extent -5.5,-5.15 5.5,5.15, body extent -5.5,-5.15 5.5,5.15, height 4
WEEE_Minimum [mil] "WEEElie bin"
  silkscreen extent -95,-172 99,104

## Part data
C1 C7: library part CMP-0006669-2, "CAP, CERM, 0.047 uF, 25 V, +/- 10%, X7R, 0402", Cap_Case=0402, Manufacturer=MuRata, Supplier Part Number 1=490-3254-1-ND, TempCo=X7R, Tolerance_%=10%, Value1=Unknown, Value2=25V, ValueDisplayed=0.047uF
C2 C3 C4 C5 C8 C9 C10 C20 C21 C23 C24: library part CMP-0007501-5, "CAP, CERM, 10 uF, 25 V, +/- 20%, X5R, 0603", Cap_Case=0603, Manufacturer=MuRata, Supplier Part Number 1=490-12323-1-ND, TempCo=X5R, Tolerance_%=20%, Value1=Unknown, Value2=25V, ValueDisplayed=10uF
C6 C11 C12 C19 C25: library part CMP-0064946-2, "CAP, CERM, 0.1 uF, 50 V,+/- 10%, X7R, 0402", Cap_Case=0402, Manufacturer=TDK, Supplier Part Number 1=445-173610-1-ND, TempCo=X7R, Tolerance_%=10%, Value1=Unknown, Value2=50V, ValueDisplayed=0.1uF
C13 C14 C15 C16 C17: library part CMP-0007828-2, "CAP, CERM, 10 uF, 25 V, +/- 10%, X5R, 0805", Cap_Case=0805, Manufacturer=TDK, Supplier Part Number 1=445-5984-1-ND, TempCo=X5R, Tolerance_%=10%, Value1=Unknown, Value2=25V, ValueDisplayed=10uF
C18: library part CMP-0007341-5, "CAP, CERM, 4.7 uF, 16 V, +/- 10%, X5R, 0603", Cap_Case=0603, Manufacturer=MuRata, Supplier Part Number 1=490-10481-1-ND, TempCo=X5R, Tolerance_%=10%, Value1=Unknown, Value2=16V, ValueDisplayed=4.7uF
C22: library part CMP-0006235-2, "CAP, CERM, 1000 pF, 50 V, +/- 10%, X7R, 0402", Cap_Case=0402, Manufacturer=Kemet, Supplier Part Number 1=399-1032-1-ND, TempCo=X7R, Tolerance_%=10%, Value1=Unknown, Value2=50V, ValueDisplayed=1000pF
C26: library part CMP-0011556-2, "CAP, TA, 100 uF, 6.3 V, +/- 20%, 0.015 ohm, SMD", Cap_Case=3528-21, Manufacturer=Kemet, Supplier Part Number 1=399-5306-1-ND, Tolerance_%=20%, Value1="0.015 ohm", Value2=6.3V, ValueDisplayed=100uF
C27 C28: library part CMP-0009208-2, "CAP, CERM, 47 uF, 10 V, +/- 10%, X5R, 1210", Cap_Case=1210, Manufacturer=MuRata, Supplier Part Number 1=81-GRM32ER61A476KE20, TempCo=X5R, Tolerance_%=10%, Value1="0.001 ohm", Value2=10V, ValueDisplayed=47uF
C29 C30: library part CMP-0009228-2, "CAP, CERM, 4.7 uF, 50 V, +/- 10%, X7R, 1210", Cap_Case=1210, Manufacturer=MuRata, Supplier Part Number 1=490-1864-1-ND, TempCo=X7R, Tolerance_%=10%, Value1="0.002 ohm", Value2=50V, ValueDisplayed=4.7uF
C31: library part CMP-0008154-2, "CAP, CERM, 0.01 uF, 50 V, +/- 10%, X7R, 0805", Cap_Case=0805, Manufacturer=MuRata, Supplier Part Number 1=490-1664-1-ND, TempCo=X7R, Tolerance_%=10%, Value1=Unknown, Value2=50V, ValueDisplayed=0.01uF
C32: library part CMP-0007443-4, "CAP, CERM, 2200 pF, 50 V, +/- 10%, X7R, 0603", Cap_Case=0603, Manufacturer=MuRata, Supplier Part Number 1=490-1500-1-ND, TempCo=X7R, Tolerance_%=10%, Value1=Unknown, Value2=50V, ValueDisplayed=2200pF
C33: library part CMP-0006727-4, "CAP, CERM, 0.01 uF, 100 V, +/- 10%, X7R, 0603", Cap_Case=0603, Manufacturer=AVX, Supplier Part Number 1=478-1205-1-ND, TempCo=X7R, Tolerance_%=10%, Value1="0.098 ohm", Value2=100V, ValueDisplayed=0.01uF
C34: library part CMP-0007196-4, "CAP, CERM, 22 pF, 50 V, +/- 5%, C0G/NP0, 0603", Cap_Case=0603, Manufacturer=MuRata, Supplier Part Number 1=490-1411-1-ND, TempCo=C0G/NP0, Tolerance_%=5%, Value1=Unknown, Value2=50V, ValueDisplayed=22pF
C35 C36 C37: library part CMP-0006339-4, "CAP, CERM, 10 uF, 10 V, +/- 20%, X5R, 0402", Cap_Case=0402, Manufacturer="Samsung Electro-Mechanics", TempCo=X5R, Tolerance_%=20%, Value1=Unknown, Value2=10V, ValueDisplayed=10uF
C38 C39: library part CMP-0007844-2, "CAP, CERM, 22 uF, 35 V, +/- 20%, X5R, 0805", Cap_Case=0805, Manufacturer=TDK, Supplier Part Number 1=445-14428-1-ND, TempCo=X5R, Tolerance_%=20%, Value1="0.00205 ohm", Value2=35V, ValueDisplayed=22uF
C40 C43: library part CMP-0006370-2, "CAP, CERM, 0.1 uF, 35 V, +/- 10%, X5R, 0402", Cap_Case=0402, Manufacturer="Taiyo Yuden", Supplier Part Number 1=587-1994-1-ND, TempCo=X5R, Tolerance_%=10%, Value1=Unknown, Value2=35V, ValueDisplayed=0.1uF
C41 C42: library part CMP-0009779-2, "CAP, CERM, 330 pF, 50 V, +/- 10%, X7R, 0201", Cap_Case=0201, Manufacturer=MuRata, Supplier Part Number 1=GRM033R71H331KA12D-ND, TempCo=X7R, Tolerance_%=10%, Value1=Unknown, Value2=50V, ValueDisplayed=330pF
C44: library part CMP-0007357-5, "CAP, CERM, 4.7 uF, 35 V, +/- 10%, X5R, 0603", Cap_Case=0603, Manufacturer=MuRata, Supplier Part Number 1=490-7205-1-ND, TempCo=X5R, Tolerance_%=10%, Value1=Unknown, Value2=35V, ValueDisplayed=4.7uF
C45 C46 C47 C48: library part CMP-0006236-2, "CAP, CERM, 0.01 uF, 50 V, +/- 5%, X7R, 0402", Cap_Case=0402, Manufacturer=Kemet, Supplier Part Number 1=399-7758-1-ND, TempCo=X7R, Tolerance_%=5%, Value1=Unknown, Value2=50V, ValueDisplayed=0.01uF
D1: library part CMP-0002827-3, "LED, Green, SMD", Color=green, Manufacturer=Lite-On, Power_TotalModule=100mW, Value1=0.1W, Value2=2.1V
D2: library part CMP-0028510-2, "Diode, Schottky, 40 V, 5 A, SMC", Manufacturer="Comchip Technology", Value1=5A, Value2=0.55V
J1 J2: library part CMP-0074910-1, "Terminal Block, 5.08 mm, 2x1, Brass, TH", Color=Blue, Current_A=15A, Manufacturer="On-Shore Technology", Supplier Part Number 1=ED1609-ND, Voltage_V=300V
J3: library part CMP-0055448-2, "Header (shrouded), 100mil, 5x2, High-Temperature, Gold, TH", Manufacturer=3M, Supplier Part Number 1=MHC10K-ND
J4: library part CMP-0055341-2, "Terminal Block, 3.5 mm, 2x1, Tin, TH", Manufacturer=Molex, Supplier Part Number 1=WM7877-ND
J5: library part CMP-0055598-2, "Header, 2.54mm, 5x2, Gold, SMT", Color=Black, Current_A=5.4A, Manufacturer=Samtec, Supplier Part Number 1=SAM8741-ND, Voltage_V=475V
J6: library part CMP-0085712-2, "Receptacle, USB 3.1 Type C, R/A, Gold, SMT", Color=Black, Current_A=1.25A, Manufacturer="JAE Electronics", Voltage_V=20V
J7: library part CMP-0054562-1, "Header, 100mil, 4x1, Tin, TH", Color=Black, Current_A=3A, Manufacturer="Sullins Connector Solutions", Supplier Part Number 1=S1012E-04-ND, Voltage_V=1.8kV
JP1 JP2 JP3 JP4: library part CMP-0002337-1, "Header, 100mil, 2x1, Tin, TH", Color=Black, Current_A=3A, Manufacturer="Sullins Connector Solutions", PartNumber=PEC02SAAN, Supplier Part Number 1=S1012E-02-ND, Voltage_V=1.8kV
L1: library part CMP-0063290-1, "Inductor, Shielded Drum Core, Powdered Iron, 1 uH, 7 A, 0.0181 ohm, SMD", Manufacturer=Vishay-Dale, Supplier Part Number 1=541-1218-1-ND, Value1="0.0181 ohm", Value2=7A, ValueDisplayed=1uH
L2: library part CMP-0064124-1, "Inductor, Shielded Drum Core, Powdered Iron, 4.7 uH, 7 A, 0.015 ohm, SMD", Manufacturer="Wurth Elektronik", Supplier Part Number 1=732-3389-1-ND, Value1="0.015 ohm", Value2=7A, ValueDisplayed=4.7uH
L3: library part CMP-0003375-1, "Ferrite Bead, 21 ohm @ 100 MHz, 6 A, 0805", Manufacturer="Taiyo Yuden", Supplier Part Number 1=587-1765-1-ND, Value1="0.004 ohm", Value2=6A, ValueDisplayed="21 ohm"
Logo1: library part CMP-0074844-1
Logo2: library part CMP-0074838-1, "Texas Instrument Corporate Signature"
Logo3: library part CMP-0074847-1, "FCC_disclaimer"
Logo4: library part CMP-0074769-1
LOGO5: library part CMP-0074837-1, "IEC 61010-1 Hot Surface Warning"
NT1: library part CMP-0078142-3, "Single point connection between nets.", Manufacturer=N/A
R1: library part CMP-0022736-4, "RES, 100, 1%, 0.1 W, 0603", Manufacturer=Yageo, Power_W=100mW, Supplier Part Number 1=311-100HRCT-ND, TempCo="100 ppm/C", Tolerance_%=1%, Value2=0.1W, Value_Code=100R, ValueDisplayed=100
R2: library part CMP-0026232-2, "RES, 2.21 k, 1%, 0.063 W, AEC-Q200 Grade 0, 0402", Manufacturer=Vishay-Dale, Power_W=63mW, Supplier Part Number 1=541-2.21KLCT-ND, TempCo="100 ppm/C", Tolerance_%=1%, Value2=0.063W, Value_Code=2k21, ValueDisplayed=2.21k
R3: library part CMP-0026464-2, "RES, 5.23 k, 1%, 0.063 W, AEC-Q200 Grade 0, 0402", Manufacturer=Vishay-Dale, PartNumber=CRCW04025K23FKED, Power_W=63mW, Supplier Part Number 1=541-5.23KLCT-ND, TempCo="100 ppm/C", Tolerance_%=1%, Value2=0.063W, Value_Code=5k23, ValueDisplayed=5.23k
R4: library part CMP-0022788-4, "RES, 137 k, 1%, 0.1 W, 0603", Manufacturer=Yageo, Power_W=100mW, Supplier Part Number 1=311-137KHRCT-ND, TempCo="100 ppm/C", Tolerance_%=1%, Value2=0.1W, Value_Code=137k
R5: library part CMP-0026284-2, "RES, 30.1 k, 1%, 0.063 W, AEC-Q200 Grade 0, 0402", Manufacturer=Vishay-Dale, PartNumber=CRCW040230K1FKED, Power_W=63mW, Supplier Part Number 1=541-30.1KLCT-ND, TempCo="100 ppm/C", Tolerance_%=1%, Value2=0.063W, Value_Code=30k1, ValueDisplayed=30.1k
R6: library part CMP-0022735-5, "RES, 100 k, 1%, 0.1 W, 0603", Manufacturer=Yageo, Power_W=100mW, Supplier Part Number 1=311-100KHRCT-ND, TempCo="100 ppm/C", Tolerance_%=1%, Value2=0.1W, Value_Code=100k
R7: library part CMP-0025958-3, "RES, 10.0 k, 1%, 0.063 W, AEC-Q200 Grade 0, 0402", Manufacturer=Vishay-Dale, PartNumber=CRCW040210K0FKED, Power_W=63mW, Supplier Part Number 1=541-10.0KLCT-ND, TempCo="100 ppm/C", Tolerance_%=1%, Value2=0.063W, Value_Code=10k0, ValueDisplayed=10.0k
R8: library part CMP-0023246-5, "RES, 6.04 k, 1%, 0.1 W, 0603", Manufacturer=Yageo, Power_W=100mW, Supplier Part Number 1=311-6.04KHRCT-ND, TempCo="100 ppm/C", Tolerance_%=1%, Value2=0.1W, Value_Code=6k04, ValueDisplayed=6.04k
R9: library part CMP-0022000-4, "RES, 10.5 k, 1%, 0.1 W, AEC-Q200 Grade 0, 0603", Manufacturer=Vishay-Dale, Power_W=100mW, Supplier Part Number 1=541-10.5KHCT-ND, TempCo="100 ppm/C", Tolerance_%=1%, Value2=0.1W, Value_Code=10k5, ValueDisplayed=10.5k
R10: library part CMP-0022089-4, "RES, 17.4 k, 1%, 0.1 W, AEC-Q200 Grade 0, 0603", Manufacturer=Vishay-Dale, Power_W=100mW, Supplier Part Number 1=541-17.4KHCT-ND, TempCo="100 ppm/C", Tolerance_%=1%, Value2=0.1W, Value_Code=17k4, ValueDisplayed=17.4k
R11: library part CMP-0017299-3, "RES, 10.0, 1%, 0.25 W, AEC-Q200 Grade 0, 1206", Manufacturer=Panasonic, Power_W=250mW, Supplier Part Number 1=P10.0FCT-ND, TempCo="100 ppm/C", Tolerance_%=1%, Value2=0.25W, Value_Code=10R0, ValueDisplayed=10.0
R12: library part CMP-0022483-4, "RES, 51.1, 1%, 0.1 W, AEC-Q200 Grade 0, 0603", Manufacturer=Vishay-Dale, Power_W=100mW, Supplier Part Number 1=541-51.1HCT-ND, TempCo="100 ppm/C", Tolerance_%=1%, Value2=0.1W, Value_Code=51R1, ValueDisplayed=51.1
R13: library part CMP-0022546-4, "RES, 665 k, 1%, 0.1 W, AEC-Q200 Grade 0, 0603", Manufacturer=Vishay-Dale, Power_W=100mW, Supplier Part Number 1=541-665KHCT-ND, TempCo="100 ppm/C", Tolerance_%=1%, Value2=0.1W, Value_Code=665k
R14: library part CMP-0021999-4, "RES, 10.2 k, 1%, 0.1 W, AEC-Q200 Grade 0, 0603", Manufacturer=Vishay-Dale, Power_W=100mW, Supplier Part Number 1=541-10.2KHCT-ND, TempCo="100 ppm/C", Tolerance_%=1%, Value2=0.1W, Value_Code=10k2, ValueDisplayed=10.2k
R15: library part CMP-0022036-4, "RES, 130 k, 1%, 0.1 W, AEC-Q200 Grade 0, 0603", Manufacturer=Vishay-Dale, Power_W=100mW, Supplier Part Number 1=541-130KHCT-ND, TempCo="100 ppm/C", Tolerance_%=1%, Value2=0.1W, Value_Code=130k
R16: library part CMP-0022137-4, "RES, 1.96 k, 1%, 0.1 W, AEC-Q200 Grade 0, 0603", Manufacturer=Vishay-Dale, Power_W=100mW, Supplier Part Number 1=541-1.96KHCT-ND, TempCo="100 ppm/C", Tolerance_%=1%, Value2=0.1W, Value_Code=1k96, ValueDisplayed=1.96k
R17: library part CMP-0022360-4, "RES, 37.4 k, 1%, 0.1 W, AEC-Q200 Grade 0, 0603", Manufacturer=Vishay-Dale, Power_W=100mW, Supplier Part Number 1=541-37.4KHCT-ND, TempCo="100 ppm/C", Tolerance_%=1%, Value2=0.1W, Value_Code=37k4, ValueDisplayed=37.4k
R21 R22 R24 R25: library part CMP-0027272-3, "RES, 2.20 k, 1%, 0.05 W, 0201", Manufacturer=Vishay-Dale, Power_W=50mW, Supplier Part Number 1=541-2.20KAABCT-ND, TempCo="100 ppm/C", Tolerance_%=1%, Value2=0.05W, Value_Code=2k20, ValueDisplayed=2.20k
R26 R27 R29: library part CMP-0027008-4, "RES, 0, 5%, 0.05 W, 0201", Manufacturer=Vishay-Dale, Power_W=50mW, Supplier Part Number 1=72M6743, TempCo=ppm/C, Tolerance_%=5%, Value2=0.05W, Value_Code=0000, ValueDisplayed=0
R28 R30 R31 R32: library part CMP-0027262-3, "RES, 10.0 k, 1%, 0.05 W, 0201", Manufacturer=Vishay-Dale, Power_W=50mW, Supplier Part Number 1=541-10.0KAABCT-ND, TempCo="100 ppm/C", Tolerance_%=1%, Value2=0.05W, Value_Code=10k0, ValueDisplayed=10.0k
TP1: library part CMP-0055137-1, "Test Point, Miniature, Red, TH", Color=Red, Manufacturer=Keystone, Supplier Part Number 1=36-5000-ND
TP2 TP3: library part CMP-0055153-1, "Test Point, Compact, SMT", Manufacturer=Keystone, Supplier Part Number 1=36-5016TR-ND
U1: library part CMP-0088656-1, "BQ2579x HotRod", Manufacturer="Texas Instruments", Operating Temperature Range=to
U2: library part CMP-0074640-3, "500-mA, Low IQ, Small Size, Low Dropout Regulator, DBV0005A (SOT-23-5)", Alternate Manufacturer="Texas Instruments"
U3: library part CMP-0067056-2, "3.5V to 28V Input, 5A, 570kHz Step-Down Converter with Eco-mode, DDA0008E (SOIC-8)", Alternate Manufacturer="Texas Instruments", Alternate PartNumber=TPS54531DDA
U4: library part CMP-0090338-2, "USB Type-C and USB PD Controller with Integrated Power Switches Optimized for Power Applications", Manufacturer="Texas Instruments", Max Supply Voltage=22V, Min Supply Voltage=3V, Operating Temperature Range="-40°C to +125°C"
U5: library part CMP-0005314-2, "256 kb I2C CMOS Serial EEPROM, SOIC-8", Manufacturer="ON Semiconductor", Supplier Part Number 1=CAT24C256WI-G-ND
U6: library part CMP-0077834-1, "22-V Precision Surge Protection Clamp, DRV0006A (WSON-6)", Alternate Manufacturer="Texas Instruments"
ZZ1: library part CMP-0003616-3

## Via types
v1: diameter 20, hole 10, Top Layer to Bottom Layer, tented both sides, 445 vias
v2: diameter 23.62, hole 11.81, Top Layer to Bottom Layer, tented both sides, 24 vias
v3: diameter 30, hole 15, Top Layer to Bottom Layer, tented both sides, 12 vias
v4: diameter 19.68, hole 7.87, Top Layer to Bottom Layer, tented both sides, 10 vias
v5: diameter 20, hole 10, Top Layer to Bottom Layer, 3 vias

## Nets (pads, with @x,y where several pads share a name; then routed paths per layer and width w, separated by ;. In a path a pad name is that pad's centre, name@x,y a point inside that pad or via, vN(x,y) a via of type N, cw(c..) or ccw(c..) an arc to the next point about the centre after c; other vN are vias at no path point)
AGND: C22.2 J3.6 J4.2 NT1.2 R5.1 R6.1 R7.1 R8.1 R9.1 R10.1 U1.10 U1.11 U1.13 | length 281.9
  Top Layer w10: 940.94,2141.73 941.06,2141.61 U1.13@941.06,2110.14 ; 972.44,2131.89 972.44,2110.25 U1.11@972.56,2110.14 ; 988.19,2133.86 988.31,2133.74 U1.10@988.31,2110.14
  Bottom Layer w10: J4.2@566.93,2856.3 606.3,2816.93 R7.1@606.3,2763.78 ; v1(602.36,2183.07) 640.93,2183.07 R6.1@641.92,2184.06 ; v1(765.75,2218.5) 765.75,2190.08 R5.1@765.87,2189.96 ; C22.2@816.06,2021.65 815.75,2021.97 815.75,2048.03 816.34,2048.62
  other v1: 805.12,2061.02 972.44,2143.7 1440.94,2673.23 1503.94,2673.23 1568.9,2673.23
BAT: C19.1 C20.1 C21.1 J2.2 R1.1 U1.22 U1.23 | length 977.6
  Top Layer w10: J2.2@167.32,2342.91 369.68,2342.91 417.32,2295.28 417.32,2167.32 602.36,1982.28 v1(668.92,1982.28) 704.84,1982.28 C21.1@708.78,1978.35 C20.1@767.83,1978.35 811.14,1978.35 817.05,1972.44 ; 817.05,1970.47 817.05,1972.44 ; 873.15,1996.06 853.46,1996.06 833.89,1976.49 821.1,1976.49 817.05,1972.44
  Bottom Layer w10: R1.1@639.76,1980.31 641.73,1978.35 645.67,1982.28 v1(668.92,1982.28)
C_CC1: C42.1 J6.A5 U4.28 | length 942.2
  Top Layer w6: J6.A5@296.26,1534.45 296.75,1533.96 326.28,1533.96 v1(326.77,1533.46) ; v1(1120.87,1551.18) 1153.44,1551.18 1170.47,1534.15 C42.1@1170.47,1531.5 1219.12,1531.5 U4.28@1219.3,1531.68
  Signal Layer 2 w6: v1(326.77,1533.46) 328.74,1531.5 1101.18,1531.5 v1(1120.87,1551.18)
C_CC2: C41.1 J6.B5 U4.29 | length 1095.8
  Top Layer w6: v1(194.88,1470.47) 209.65,1485.24 J6.B5@233.27,1485.24 ; v1(1122.05,1482.28) 1155.41,1482.28 1170.47,1497.35 C41.1@1170.47,1500 1185.04,1500 1200.97,1515.93 U4.29@1219.3,1515.93
  Signal Layer 2 w6: v1(194.88,1470.47) 197.52,1470.47 205.4,1462.6 1078.74,1462.6 1098.43,1482.28 v1(1122.05,1482.28)
C_USB_N: J6.A7 J6.B7 U4.27 | length 1182
  Top Layer w6: v1(194.88,1527.56) 197.83,1524.61 J6.B7@233.27,1524.61 ; J6.A7@296.26,1495.08 321.85,1495.08 v1(327.7,1489.23) ; v1(1061.02,1490.16) 1061.02,1517.72 1114.98,1571.68 1178.32,1571.68 1201.64,1548.36 1218.36,1548.36 U4.27@1219.3,1547.43
  Signal Layer 2 w6: v1(327.7,1489.23) 329.3,1489.23 338.21,1480.32 1050.51,1480.32 v1@1060.69,1490.49
  Bottom Layer w6: v1(194.88,1527.56) 242.13,1527.56 280.45,1489.23 v1(327.7,1489.23) ; v1@1060.35,1490.16 v1(1061.02,1490.16)
C_USB_P: J6.A6 J6.B6 U4.26 | length 1175.4
  Top Layer w6: v1(194.88,1499.56) 198.67,1499.56 204.03,1504.92 J6.B6@233.27,1504.92 ; J6.A6@296.26,1514.76 333.81,1514.76 336.76,1511.81 v1(340.55,1511.81) ; v1(1037.4,1501.97) 1037.95,1502.51 1037.95,1516.29 1106.3,1584.65 1185.04,1584.65 1205.58,1564.11 1218.36,1564.11 U4.26@1219.3,1563.17
  Signal Layer 2 w6: v1(194.88,1499.56) 198.67,1499.56 203.05,1503.94 277.56,1503.94 288.39,1514.76 330.04,1514.76 330.31,1514.49 337.87,1514.49 v1(340.55,1511.81) ; v1@339.07,1513.29 350.39,1501.97 v1(1037.4,1501.97)
GND: C2.1 C3.1 C4.1 C5.1 C6.2 C8.1 C9.1 C10.1 C11.2 C12.2 C13.2 C14.2 C15.2 C16.2 C17.2 C18.2 C19.2 C20.2 C21.2 C23.1 C24.1 C26.2 C27.2 C28.2 C29.2 C30.2 C31.2 C33.2 C34.2 C35.2 C36.2 C37.2 C38.2 C39.2 C40.2 C41.2 C42.2 C43.2 C44.2 C45.1 C46.1 C47.1 C48.1 D2.2 J1.2 J2.1 J6.A1 J6.A12 J6.B1 J6.B12 J6.S1 J6.S2 J6.S3 J6.S4 J7.4 NT1.1 R15.1 R16.1 R17.1 R28.1 R29.1 R30.1 R31.1 R32.1 TP2.1 TP3.1 U1.27 U2.2 U3.7 U3.9@577.76,987.91 U4.5 U4.11 U4.12 U4.14 U4.31 U4.39 U5.4 U6.1 U6.2 U6.3 U6.7@451.77,1610.24 | length 821
  Top Layer w8: U4.31@1219.3,1484.43 1241.74,1484.43
  Top Layer w10: 948.94,1996.06 U1.27@948.94,1968.4 948.94,1879.92 v3(949.92,1879.92) ; v1(1224.41,1338.58) 1224.41,1341.29 1239.73,1356.61 1239.73,1365.89 1241.11,1367.27 1241.11,1376.32 1281.21,1416.42 1294.1,1429.31 U4.39@1294.1,1430.69 ; 1241.74,1484.43 1281.21,1444.96 U4.39@1294.1,1432.07 ; U4.39@1307.69,1417.11 U4.39@1294.1,1430.69 ; U4.39@1307.69,1444.28 U4.39@1294.1,1430.69 ; U4.39@1315.66,1453.63 1346.46,1484.43 U4.14@1368.91,1484.43 ; U4.39@1316.35,1452.94 U4.12@1368.91,1452.94 U4.39@1334.26,1452.94 ; U4.5@1317.72,1354.51 U4.39@1317.72,1407.07 ; U4.39@1334.26,1437.19 U4.11@1368.91,1437.19
  Top Layer w15: 948.94,1996.06 v1@948.94,2041.53
  Signal Layer 1 w15: v1(948.94,2041.55) 949.06,2041.43 949.06,1880.79 v3(949.92,1879.92)
  other v1: 108,66 208,66 308,66 408,66 508,66 608,66 708,66 808,66 908,66 1008,66 1108,66 1208,66 1308,66 1408,66 1508,66 1608,66 1708,66 1808,66 1908,66 158,166 258,166 358,166 458,166 558,166 658,166 758,166 858,166 958,166 1058,166 1158,166 1258,166 1358,166 1458,166 1558,166 1658,166 1758,166 1858,166 1958,166 108,266 208,266 308,266 408,266 508,266 608,266 708,266 808,266 908,266 1008,266 1108,266 1208,266 1308,266 1408,266 158,366 258,366 358,366 458,366 558,366 658,366 758,366 858,366 958,366 1058,366 1158,366 1258,366 1358,366 1958,366 108,466 208,466 308,466 408,466 508,466 608,466 708,466 808,466 908,466 1008,466 1108,466 1208,466 1308,466 1408,466 158,566 258,566 358,566 458,566 558,566 658,566 758,566 858,566 958,566 1058,566 1158,566 1258,566 1358,566 1458,566 1658,566 1758,566 1858,566 1958,566 108,666 208,666 308,666 408,666 508,666 608,666 708,666 808,666 908,666 1008,666 1108,666 1208,666 1308,666 1408,666 1608,666 1708,666 1808,666 1908,666 158,766 258,766 358,766 458,766 558,766 658,766 758,766 858,766 958,766 1058,766 1158,766 1258,766 1358,766 1458,766 1658,766 1758,766 1858,766 1958,766 651.57,807.09 1202.76,830.71 1387.48,832.68 651.57,838.58 108,866 208,866 308,866 1608,866 1708,866 1808,866 1908,866 158,966 258,966 858,966 1758,966 1858,966 1958,966 1476.06,986.22 852.36,1003.94 852.36,1062.99 308,1066 1608,1066 1708,1066 433.07,1102.36 852.36,1122.05 738.19,1125.98 258,1166 1258,1166 1558,1166 1658,1166 1758,1166 1958,1166 753.94,1167.32 1285.43,1198.82 854.33,1200.79 685.04,1210.63 777.56,1216.54 108,1266 208,1266 308,1266 808,1266 1508,1266 1708,1266 777.56,1289.37 777.56,1330.71 1358.27,1338.58 1151.57,1356.3 358,1366 858,1366 1658,1366 1758,1366 1958,1366 777.56,1377.95 1151.57,1385.83 777.56,1417.32 108,1466 1408,1466 1608,1466 1708,1466 1120.08,1515.75 158,1566 1458,1566 1758,1566 1958,1566 1393.7,1596.46 1415.35,1643.7 622.05,1653.54 663.39,1653.54 714.57,1653.54 1508,1666 775.59,1667.32 407.48,1669.29 438.98,1669.29 1450.79,1732.28 158,1766 258,1766 358,1766 458,1766 1158,1766 1458,1766 1958,1766 626.27,1779.52 665.35,1779.53 706.69,1779.53 750,1779.53 795.28,1779.53 1100.39,1809.06 1131.89,1809.06 1163.39,1809.06 1196.85,1809.06 1452.76,1820.87 108,1866 1408,1866 1508,1866 1708,1866 1808,1866 1758,1966 1958,1966 785.43,2015.75 308,2066 408,2066 1408,2066 1508,2066 1708,2066 1808,2066 1112.2,2070.87 679.13,2076.77 718.5,2076.77 755.91,2076.77 1224.41,2092.52 1279.53,2092.52 1181.1,2094.49 1187.01,2124.02 158,2166 258,2166 358,2166 1258,2166 1358,2166 1758,2166 1958,2166 108,2266 608,2266 708,2266 1008,2266 1208,2266 1308,2266 1408,2266 1508,2266 1708,2266 458,2366 558,2366 658,2366 758,2366 958,2366 1058,2366 1258,2366 1358,2366 1558,2366 1958,2366 108,2466 208,2466 308,2466 408,2466 508,2466 608,2466 708,2466 1008,2466 1208,2466 1308,2466 1408,2466 1708,2466 1808,2466 1908,2466 258,2566 358,2566 458,2566 558,2566 658,2566 758,2566 1958,2566 108,2666 208,2666 308,2666 408,2666 508,2666 608,2666 708,2666 808,2666 1108,2666 1208,2666 1308,2666 1708,2666 1808,2666 1908,2666 158,2766 258,2766 358,2766 458,2766 558,2766 758,2766 1658,2766 1758,2766 1858,2766 1958,2766 108,2866 208,2866 308,2866 408,2866 508,2866 1008,2866 1108,2866 1408,2866 1508,2866 1608,2866 1708,2866 1808,2866 1908,2866
  other v2: 1253.95,1389.35 1280.72,1389.35 1307.49,1389.35 1334.26,1389.35 1253.95,1416.91 1280.72,1416.91 1307.49,1416.91 1334.26,1416.91 1253.95,1444.47 1280.72,1444.47 1307.49,1444.47 1334.26,1444.47 1253.95,1472.03 1280.72,1472.03 1307.49,1472.03 1334.26,1472.03
  other v3: 918.43,1879.92 981.42,1879.92 926.29,2057.07 971.57,2057.09 948.92,2078.94
  other v4: 500.98,966.26 552.17,966.26 603.35,966.26 654.53,966.26 500.98,1009.57 552.17,1009.57 603.35,1009.57 654.53,1009.57 430.12,1610.24 473.43,1610.24
I2C1_IRQ: U4.10 | length 207.9
  Top Layer w6: U4.10@1368.91,1421.44 1411.6,1421.44 v1(1417.32,1427.17)
  Bottom Layer w6: v1(1417.32,1427.17) 1468.5,1427.17 1527.56,1368.11 1527.56,1345.67
I2C1_SCL: J3.9 U4.9 | length 1930.2
  Top Layer w6: U4.9@1368.91,1405.69 1369.84,1404.76 1396.54,1404.76 1403.65,1397.64 v1(1417.32,1397.64) 1537.4,1397.64 1632.87,1302.17 v5@1633.86,1301.18
  Top Layer w10: v5(1663.39,2578.74) 1787.4,2578.74 1789.37,2576.77 1812.99,2576.77 J3.9@1863.19,2626.97
  Signal Layer 2 w10: v5(1633.86,1303.15) 1633.86,1418.88 1663.39,1448.41 1663.39,1458.66 1664.61,2577.52 v5(1663.39,2578.74)
  Bottom Layer w6: v1(1417.32,1397.64) 1464.57,1397.64 1496.06,1366.14 1496.06,1345.67
I2C1_SDA: J3.10 U4.8 | length 1844.8
  Top Layer w6: U4.8@1368.91,1389.94 1369.84,1389.01 1382.65,1389.01 1403.54,1368.11 v1(1417.32,1368.11) 1535.43,1368.11 v1(1592.52,1311.02) v1@1592.52,1309.06
  Top Layer w10: v5(1633.86,2627.95) J3.10@1763.19,2626.97
  Signal Layer 2 w10: v1(1592.52,1311.02) 1592.52,1425.2 1604.33,1437.01 1614.17,1437.01 1631.89,1454.72 1631.89,2675.2 ; v5(1633.86,2627.95) v5@1633.86,2629.92
  Bottom Layer w6: v1(1417.32,1368.11) 1460.63,1368.11 1468.5,1360.24 1468.5,1345.67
